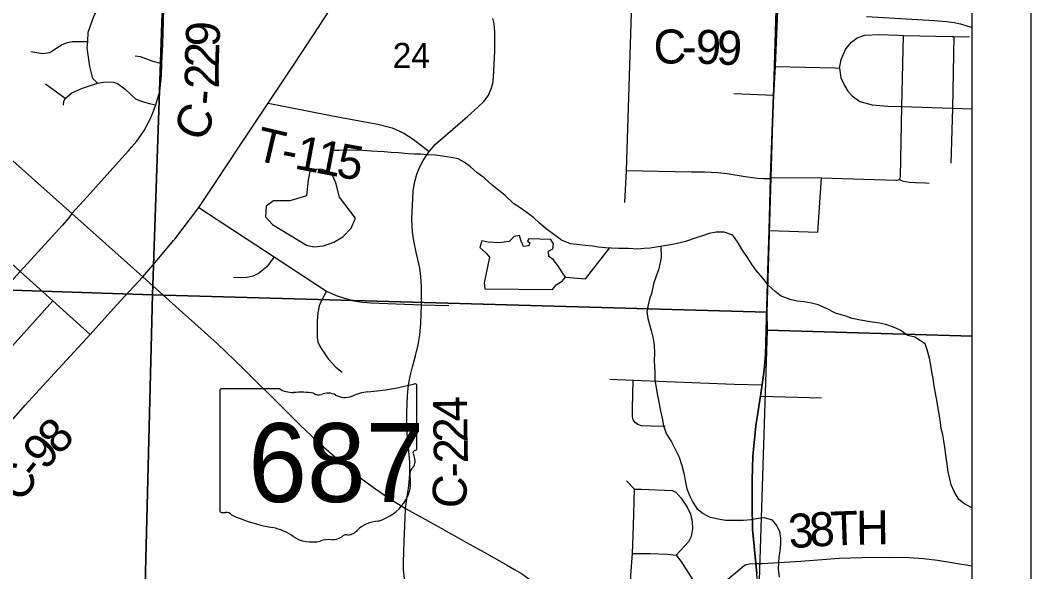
# Model space of a CAD drawing. Extents: x 0 to 34, y 0 to 22.
# Drawn here: x 8.046 to 9.735, y 16.375 to 17.297 of the extents above; entities that cross this region are included whole.
import ezdxf

# ---------------------------------------------------------------- set-up
doc = ezdxf.new("R2010")
doc.units = 0
for name, color, linetype in [('GM_X_Corporation', 7, 'Continuous'), ('GM_X_County_Road', 7, 'Continuous'), ('GM_X_County_Road_Text', 7, 'Continuous'), ('GM_X_Interchange_Ramps', 7, 'Continuous'), ('GM_X_Minor_Lake', 7, 'Continuous'), ('GM_X_Minor_River', 7, 'Continuous'), ('GM_X_Section_Text', 7, 'Continuous'), ('GM_X_State_Location', 7, 'Continuous'), ('GM_X_State_Route', 7, 'Continuous'), ('GM_X_State_Shield', 7, 'Continuous'), ('GM_X_Township_Road', 7, 'Continuous'), ('GM_X_Township_Road_Text', 7, 'Continuous'), ('SH_Data', 7, 'Continuous')]:
    doc.layers.add(name, color=color, linetype=linetype)

msp = doc.modelspace()

# ---------------------------------------------------------------- linework, layer by layer
at = {"layer": 'GM_X_Corporation'}
for points in [[(7.1023, 20.9204), (2.837, 20.9204), (2.837, 14.1204), (9.637, 14.1204), (9.637, 20.9204), (9.4036, 20.9204), (9.4022, 20.8667), (9.2273, 20.8723), (9.1354, 20.8749), (9.124, 20.8753), (8.9858, 20.878), (8.9676, 20.8785), (8.8663, 20.881), (8.6259, 20.8892), (8.5535, 20.8914), (8.5421, 20.8915), (8.4667, 20.8934), (8.0602, 20.9055), (7.9522, 20.9084), (7.1104, 20.9188)], [(8.3013, 17.8445), (8.2669, 16.8377), (7.2756, 16.8704), (7.31, 17.8806)], [(8.3013, 17.8445), (9.3232, 17.8175), (9.3224, 17.7834), (9.2937, 16.8089), (8.2669, 16.8377)], [(9.637, 16.7685), (9.637, 17.7759), (9.3224, 17.7834), (9.2937, 16.8089), (9.2941, 16.7789)], [(7.2756, 16.8704), (8.2669, 16.8377), (8.2409, 15.8234), (7.2356, 15.8559)], [(8.2669, 16.8377), (9.2937, 16.8089), (9.2941, 16.7789), (9.2625, 15.7858), (8.2409, 15.8234)], [(9.637, 15.7721), (9.637, 16.7685), (9.2941, 16.7789), (9.2625, 15.7858)]]:
    msp.add_lwpolyline(points, close=True, dxfattribs=at)
for points in [[(9.637, 14.7553), (9.637, 20.8621)], [(9.3114, 17.3124), (9.3077, 17.2197), (9.305, 17.1721), (9.2999, 17.0342), (9.2999, 17.0328), (9.2978, 16.9456), (9.2955, 16.8776), (9.2915, 16.7373), (9.2893, 16.7123), (9.2861, 16.6878), (9.2832, 16.6688), (9.2753, 16.6189), (9.27, 16.568), (9.2692, 16.5283), (9.2692, 16.4875), (9.2695, 16.4459), (9.2753, 16.389), (9.277, 16.3719)], [(9.277, 16.3719), (9.2753, 16.389), (9.2695, 16.4459), (9.2692, 16.4875), (9.2692, 16.5283), (9.27, 16.568), (9.2753, 16.6189), (9.2832, 16.6688), (9.2861, 16.6878), (9.2893, 16.7123), (9.2915, 16.7373), (9.2955, 16.8776), (9.2978, 16.9456), (9.2999, 17.0328), (9.2999, 17.0342), (9.305, 17.1721), (9.3077, 17.2197), (9.3114, 17.3124)]]:
    msp.add_lwpolyline(points, dxfattribs=at)
at = {"layer": 'GM_X_County_Road'}
for points in [[(8.2322, 17.085), (8.2404, 17.0945), (8.2529, 17.1125), (8.263, 17.1315), (8.2686, 17.1447), (8.2725, 17.1552), (8.2757, 17.1669), (8.2788, 17.1781), (8.2815, 17.2043), (8.282, 17.224), (8.2827, 17.2365), (8.2837, 17.2555), (8.289, 17.4375), (8.2914, 17.5073), (8.2971, 17.722)], [(9.3084, 17.2321), (9.3116, 17.3118), (9.3117, 17.3152), (9.3116, 17.322), (9.313, 17.3683), (9.3162, 17.4807)], [(8.3019, 16.9283), (8.3038, 16.9306), (8.3439, 16.9836), (8.3711, 17.024), (8.4108, 17.0845), (8.4598, 17.1583), (8.5, 17.2183), (8.5356, 17.2723), (8.5918, 17.3583), (8.6122, 17.3882), (8.6251, 17.4058)], [(8.6898, 16.4804), (8.6919, 16.496), (8.6951, 16.5183), (8.6969, 16.5376), (8.6968, 16.5582), (8.6952, 16.5766), (8.6926, 16.6062), (8.6919, 16.6408), (8.693, 16.6693), (8.6949, 16.6871), (8.6973, 16.702), (8.7011, 16.7176), (8.7063, 16.7358), (8.7109, 16.754), (8.7137, 16.7707), (8.7154, 16.7897), (8.7163, 16.8211), (8.7161, 16.8511), (8.715, 16.8686), (8.7135, 16.8825), (8.7073, 16.9093), (8.7037, 16.9279), (8.7011, 16.9433), (8.7003, 16.9641), (8.7022, 17.0112), (8.7045, 17.0251), (8.7086, 17.0392), (8.7137, 17.0518), (8.7193, 17.0623), (8.7292, 17.0773), (8.7399, 17.0895), (8.7769, 17.1218), (8.7931, 17.1359), (8.8107, 17.1513), (8.8212, 17.1614), (8.8282, 17.1717), (8.833, 17.1822), (8.8355, 17.1909), (8.8368, 17.2017), (8.8387, 17.2449), (8.8392, 17.2776), (8.8379, 17.2909), (8.8357, 17.2997)], [(9.27, 16.5575), (9.2702, 16.5675), (9.2755, 16.6183), (9.2834, 16.6682), (9.2863, 16.6872), (9.2895, 16.7117), (9.2917, 16.7368), (9.2957, 16.8771), (9.298, 16.945), (9.3001, 17.0323), (9.3001, 17.0336), (9.3052, 17.1715), (9.3079, 17.2192), (9.3084, 17.2321)], [(8.1319, 16.9735), (8.1576, 17.0017), (8.2099, 17.0598), (8.2265, 17.0785), (8.2322, 17.085)], [(8.2503, 16.8678), (8.2773, 16.899), (8.3019, 16.9283)], [(7.8215, 16.3345), (7.8745, 16.4095), (7.8951, 16.4388), (7.9345, 16.4973), (7.9798, 16.5613), (8.0233, 16.618), (8.0538, 16.6531), (8.0831, 16.6854), (8.1425, 16.7499), (8.1623, 16.7717), (8.2065, 16.8203), (8.2503, 16.8678)], [(9.2755, 16.3885), (9.2697, 16.4453), (9.2694, 16.487), (9.2694, 16.5278), (9.27, 16.5575)], [(8.6865, 16.391), (8.6875, 16.4261), (8.689, 16.4649), (8.6898, 16.4804)], [(8.7557, 15.8512), (8.7546, 15.867), (8.7537, 15.8789), (8.7508, 15.9143), (8.7479, 15.947), (8.7472, 15.9777), (8.7487, 16.0502), (8.7492, 16.0794), (8.748, 16.1083), (8.7461, 16.1243), (8.7434, 16.1411), (8.7383, 16.1623), (8.7241, 16.213), (8.7053, 16.2774), (8.6958, 16.3127), (8.6918, 16.331), (8.6898, 16.3442), (8.688, 16.3634), (8.6865, 16.3782), (8.6864, 16.39), (8.6865, 16.391)], [(9.2711, 16.0327), (9.2759, 16.1303), (9.2777, 16.1911), (9.2793, 16.2525), (9.2797, 16.3303), (9.2772, 16.3713), (9.2755, 16.3885)], [(9.2755, 16.3885), (9.2857, 16.3886), (9.3505, 16.3928), (9.4145, 16.3977), (9.4529, 16.3988), (9.4993, 16.3993), (9.5317, 16.3986), (9.5555, 16.397), (9.5788, 16.3944), (9.637, 16.3849)]]:
    msp.add_lwpolyline(points, dxfattribs=at)
at = {"layer": 'GM_X_Interchange_Ramps'}
msp.add_lwpolyline([(9.4601, 17.303), (9.5742, 17.296), (9.5938, 17.2947), (9.6071, 17.2927), (9.6174, 17.2907), (9.628, 17.2876), (9.637, 17.2843)], dxfattribs=at)
at = {"layer": 'GM_X_Minor_Lake'}
for points in [[(8.5794, 17.0012), (8.573, 17.025), (8.5656, 17.0424), (8.5488, 17.0479), (8.5302, 17.0469), (8.5267, 17.0297), (8.524, 17.0031), (8.4964, 16.9947), (8.4691, 16.9951), (8.4567, 16.9862), (8.4554, 16.9683), (8.467, 16.9552), (8.524, 16.9206), (8.5362, 16.9178), (8.5528, 16.9195), (8.5698, 16.9258), (8.5849, 16.9348), (8.5987, 16.9494), (8.6061, 16.9659)], [(8.6061, 16.9659), (8.5794, 17.0012)], [(8.9355, 16.8466), (8.9414, 16.8547), (8.9516, 16.8605), (8.9572, 16.8671), (8.9533, 16.8727), (8.9444, 16.887), (8.9367, 16.8968), (8.929, 16.902), (8.9289, 16.9107), (8.9361, 16.9146), (8.9371, 16.923), (8.9324, 16.9302), (8.8956, 16.9315), (8.8938, 16.9277), (8.8976, 16.9244), (8.8958, 16.9198), (8.8867, 16.9185), (8.8828, 16.9276), (8.88, 16.937), (8.8713, 16.9354), (8.8631, 16.9269), (8.8464, 16.9244), (8.8278, 16.9257), (8.8171, 16.9278), (8.8139, 16.9171), (8.8243, 16.9074), (8.83, 16.9006), (8.8211, 16.8579), (8.822, 16.8477)], [(8.822, 16.8477), (8.9355, 16.8466)]]:
    msp.add_lwpolyline(points, dxfattribs=at)
at = {"layer": 'GM_X_Minor_River'}
for points in [[(8.8813, 16.983), (8.8706, 16.9901), (8.8563, 17.0036), (8.8452, 17.0129), (8.8345, 17.0211), (8.821, 17.0331), (8.8095, 17.0417), (8.7984, 17.0514), (8.7877, 17.0596), (8.7774, 17.0648), (8.7659, 17.0673), (8.7515, 17.0693), (8.7397, 17.0711), (8.7253, 17.072), (8.7154, 17.0726), (8.7044, 17.0729), (8.6938, 17.0735), (8.6778, 17.0748), (8.6657, 17.0757), (8.6539, 17.0767), (8.6421, 17.0773), (8.6326, 17.0779), (8.6174, 17.0789), (8.5939, 17.0793), (8.5787, 17.0791), (8.5643, 17.0792)], [(9.637, 16.4809), (9.6366, 16.4815), (9.6243, 16.4885), (9.6147, 16.4956), (9.6066, 16.5092), (9.6019, 16.5201), (9.5995, 16.5303), (9.5967, 16.5417), (9.5945, 16.5588), (9.5932, 16.5705), (9.5912, 16.5826), (9.5895, 16.5936), (9.5879, 16.6035), (9.5851, 16.6141), (9.5838, 16.6243), (9.5821, 16.6353), (9.5801, 16.6475), (9.5784, 16.6585), (9.5755, 16.6736), (9.5735, 16.6854), (9.5718, 16.6979), (9.5694, 16.7089), (9.5677, 16.7199), (9.5656, 16.7316), (9.5617, 16.7456), (9.5581, 16.7558), (9.5413, 16.767), (9.5295, 16.7699), (9.5168, 16.7784), (9.5054, 16.7836), (9.4928, 16.7883), (9.4821, 16.7901), (9.4662, 16.7925), (9.4502, 16.7953), (9.4361, 16.7982), (9.4258, 16.8018), (9.4087, 16.8073), (9.3934, 16.8147), (9.3797, 16.8209), (9.3686, 16.8238), (9.3561, 16.8259), (9.3443, 16.8273), (9.3325, 16.8298), (9.3176, 16.8353), (9.3077, 16.8435), (9.2965, 16.8532), (9.2869, 16.8656), (9.2765, 16.8776), (9.2691, 16.8878), (9.2614, 16.9002), (9.2517, 16.9138), (9.2455, 16.9247), (9.237, 16.9375), (9.2225, 16.9426), (9.2088, 16.9424), (9.1975, 16.94), (9.1862, 16.9364), (9.1756, 16.9332), (9.1578, 16.9269), (9.1465, 16.9241), (9.1359, 16.922), (9.1261, 16.92), (9.112, 16.9179), (9.0984, 16.9158), (9.0886, 16.9149), (9.0776, 16.9143), (9.0624, 16.9149), (9.0461, 16.9154), (9.0332, 16.9156), (9.0237, 16.9162), (9.0123, 16.9172), (9.0028, 16.919), (8.9902, 16.9203), (8.9804, 16.9213), (8.9652, 16.923), (8.9503, 16.9293), (8.9353, 16.9401), (8.9246, 16.9479), (8.9135, 16.9576), (8.9039, 16.9666), (8.8908, 16.9763), (8.8813, 16.983)], [(8.9572, 16.8671), (8.9906, 16.8645), (9.0306, 16.9158)], [(9.1167, 16.9186), (9.1172, 16.9001), (9.1129, 16.881), (9.1085, 16.8692), (9.1042, 16.8562), (9.1006, 16.8402), (9.0977, 16.8307), (9.0952, 16.8211), (9.093, 16.8101), (9.0947, 16.7983), (9.1003, 16.7779), (9.1031, 16.7669), (9.1052, 16.754), (9.1057, 16.7396), (9.1055, 16.7286), (9.1057, 16.7175), (9.1062, 16.7077), (9.1067, 16.6959), (9.108, 16.6864), (9.1104, 16.6724), (9.1125, 16.6618), (9.1154, 16.6459), (9.1186, 16.6315), (9.1207, 16.619), (9.1262, 16.6046), (9.1343, 16.5922), (9.1394, 16.582), (9.1472, 16.5665), (9.1515, 16.5525), (9.1555, 16.5374), (9.1572, 16.5275), (9.16, 16.5135), (9.1647, 16.5014), (9.1702, 16.4912), (9.1768, 16.4807), (9.1875, 16.4721), (9.1971, 16.4669), (9.2096, 16.4641), (9.2248, 16.4612), (9.2393, 16.4611), (9.2544, 16.4613), (9.2673, 16.4622), (9.2794, 16.4647), (9.29, 16.4656), (9.3022, 16.4616), (9.3103, 16.4518), (9.3146, 16.442), (9.3163, 16.431), (9.3164, 16.4204), (9.3154, 16.4101), (9.3137, 16.3998), (9.3128, 16.3796), (9.3145, 16.3656)]]:
    msp.add_lwpolyline(points, dxfattribs=at)
at = {"layer": 'GM_X_State_Route'}
msp.add_line((8.3168, 16.8083), (8.3316, 16.795), dxfattribs=at)
for points in [[(7.7935, 17.2806), (7.8004, 17.2734), (7.8414, 17.233), (7.8814, 17.1971), (7.9807, 17.1082), (8.1319, 16.9735), (8.2503, 16.8678), (8.3168, 16.8083)], [(8.3316, 16.795), (8.3752, 16.7559), (8.4181, 16.7144), (8.4897, 16.6437), (8.5132, 16.6205), (8.5428, 16.5921), (8.5796, 16.5597), (8.6171, 16.5298), (8.6396, 16.5133), (8.6521, 16.5047), (8.6644, 16.4961), (8.6898, 16.4804), (8.7441, 16.4504), (8.7916, 16.4239), (8.8213, 16.4074), (8.8583, 16.3867), (8.8719, 16.3787), (8.8834, 16.3717), (8.896, 16.363), (8.9057, 16.3552), (8.9153, 16.3465), (8.9343, 16.3289), (8.9639, 16.3015)]]:
    msp.add_lwpolyline(points, dxfattribs=at)
at = {"layer": 'GM_X_State_Shield'}
for p, q in [((8.379, 16.6774), (8.379, 16.4773)), ((8.4788, 16.6808), (8.3822, 16.6808)), ((8.7086, 16.5811), (8.7086, 16.6858)), ((8.7085, 16.5811), (8.7086, 16.5811))]:
    msp.add_line(p, q, dxfattribs=at)
for centre, major_axis, start_param, end_param in [((8.3828, 16.6778), (0.00382, 0), 1.712693, 3.28349), ((8.5017, 16.7041), (0.037, 0), 4.042523, 4.731795), ((8.514, 16.5685), (0.133, 0), 1.404758, 1.657858), ((8.6358, 16.6197), (0.0703, 0), 1.699011, 2.107814), ((8.5912, 16.9537), (0.3495, 0), 4.814394, 5.042369), ((8.7049, 16.6862), (0.00367, 0), 6.141152, 7.989035), ((8.5442, 16.6789), (0.0107, 0), 3.836095, 5.185415), ((8.5599, 16.6557), (0.0222, 0), 0.950623, 2.079405), ((8.5886, 16.6875), (0.0267, 0), 4.081561, 5.145723), ((8.7077, 16.5734), (0.00568, 0), 1.883978, 3.671073), ((8.7047, 16.5807), (0.00393, 0), 5.05454, 6.418171), ((8.6716, 16.5602), (0.0341, 0), 5.934695, 6.695948), ((8.7217, 16.5373), (0.0248, 0), 2.387724, 3.262537), ((8.6108, 16.524), (0.0874, 0), 5.101752, 6.440018), ((8.3828, 16.4768), (0.00385, 0), 3.00124, 4.508301), ((8.3834, 16.4973), (0.0294, 0), 4.665946, 4.897461), ((8.3894, 16.4657), (0.0106, 0), 0.519207, 1.627899), ((8.5232, 16.6455), (0.2524, 0), 4.195997, 4.488961), ((8.6476, 16.4211), (0.0479, 0), 1.647645, 2.488434), ((8.448, 16.3874), (0.079, 0), 0.823519, 1.323587), ((8.587, 16.4579), (0.0282, 0), 4.937069, 5.64225), ((8.5334, 16.4647), (0.0501, 0), 4.026481, 4.996735), ((8.5623, 16.3956), (0.0412, 0), 1.495662, 1.94098), ((8.566, 16.4498), (0.0267, 0), 4.691044, 5.507374), ((8.5902, 16.4304), (0.00752, 0), 1.147584, 2.315152)]:
    msp.add_ellipse(centre, major_axis=major_axis, ratio=0.8, start_param=start_param, end_param=end_param, dxfattribs=at)
at = {"layer": 'GM_X_Township_Road'}
for p, q in [((9.3079, 17.2192), (9.4074, 17.2169)), ((8.1204, 17.166), (8.0875, 17.19)), ((9.2385, 17.174), (9.3052, 17.1715)), ((9.3792, 16.9426), (9.3851, 17.0332)), ((9.298, 16.945), (9.3792, 16.9426)), ((9.2834, 16.6682), (9.3853, 16.6656))]:
    msp.add_line(p, q, dxfattribs=at)
for points in [[(8.1747, 17.1914), (8.1671, 17.1994), (8.1618, 17.2193), (8.1576, 17.2506), (8.1583, 17.2611), (8.1593, 17.2767), (8.1691, 17.3049), (8.1751, 17.3149), (8.1819, 17.3264), (8.1909, 17.3447), (8.1973, 17.3642), (8.2022, 17.3838), (8.2024, 17.3862), (8.2051, 17.4122), (8.2056, 17.4232), (8.2076, 17.4687), (8.2167, 17.5076)], [(9.0562, 16.9918), (9.0592, 17.0456), (9.0678, 17.3266)], [(9.4074, 17.2169), (9.4154, 17.2167), (9.4177, 17.231), (9.4255, 17.2487), (9.4354, 17.26), (9.4449, 17.2675), (9.4577, 17.2717), (9.4815, 17.2731), (9.5135, 17.2717)], [(9.5135, 17.2717), (9.5222, 17.2713), (9.6034, 17.2698)], [(9.5156, 17.0307), (9.517, 17.0348), (9.5194, 17.1523), (9.5222, 17.2713)], [(9.6064, 17.2697), (9.6039, 17.1497), (9.6014, 17.0578)], [(9.6034, 17.2698), (9.6064, 17.2697), (9.6327, 17.2692)], [(8.0632, 17.2445), (8.0733, 17.2426), (8.0827, 17.2411), (8.0949, 17.2429), (8.105, 17.2494), (8.1158, 17.2559), (8.1243, 17.2594), (8.1323, 17.261), (8.1583, 17.2611)], [(8.282, 17.224), (8.266, 17.2285), (8.2465, 17.2356), (8.2377, 17.2365)], [(9.4154, 17.2167), (9.4176, 17.2006), (9.4236, 17.1874), (9.429, 17.1784), (9.4361, 17.1702), (9.4494, 17.161), (9.4699, 17.1551), (9.4959, 17.1531), (9.5194, 17.1523), (9.6039, 17.1497), (9.637, 17.1487)], [(8.1176, 17.1546), (8.1184, 17.1609), (8.1204, 17.166), (8.1318, 17.1752), (8.1495, 17.183), (8.1747, 17.1914), (8.1848, 17.1931), (8.1948, 17.194), (8.2012, 17.1933), (8.2082, 17.1907), (8.2207, 17.1815), (8.2297, 17.1731), (8.2385, 17.1655), (8.2447, 17.1624), (8.2534, 17.1597), (8.261, 17.1577), (8.2725, 17.1552)], [(8.4598, 17.1583), (8.4827, 17.1534), (8.5677, 17.1369), (8.6126, 17.1287), (8.6431, 17.1229), (8.6673, 17.1169), (8.6868, 17.1077), (8.7022, 17.0978), (8.7292, 17.0773)], [(9.0592, 17.0456), (9.1676, 17.0435), (9.1893, 17.0432), (9.2118, 17.0424), (9.2274, 17.0406), (9.2541, 17.0359), (9.2654, 17.0343), (9.2778, 17.0329), (9.2882, 17.0323), (9.3001, 17.0323)], [(9.3001, 17.0336), (9.3851, 17.0332), (9.5095, 17.0293)], [(9.5095, 17.0293), (9.5114, 17.0293), (9.5156, 17.0307), (9.52, 17.0284), (9.525, 17.027), (9.5324, 17.0261), (9.5422, 17.0253), (9.5586, 17.025), (9.5651, 17.0244)], [(8.3439, 16.9836), (8.4699, 16.9011), (8.5576, 16.8438), (8.5737, 16.8366), (8.5891, 16.8315), (8.603, 16.8277), (8.6177, 16.8253), (8.6314, 16.8244), (8.7163, 16.8211), (8.7623, 16.8198)], [(8.1319, 16.9735), (8.1268, 16.9664), (8.1163, 16.954), (8.0456, 16.8769), (7.9421, 16.763)], [(8.1623, 16.7717), (8.1002, 16.8276), (8.0456, 16.8769), (8.0153, 16.9048), (8.0054, 16.9115), (7.996, 16.9153), (7.9838, 16.9178), (7.9487, 16.9183), (7.9406, 16.9167)], [(8.4699, 16.9011), (8.4576, 16.8845), (8.4437, 16.8734), (8.4349, 16.8692), (8.4244, 16.8666), (8.4139, 16.8659), (8.4019, 16.8666)], [(8.5576, 16.8438), (8.5488, 16.827), (8.5453, 16.8191), (8.5429, 16.8077), (8.5418, 16.7935), (8.5422, 16.7663), (8.5433, 16.7592), (8.5469, 16.7506), (8.5603, 16.7305), (8.5733, 16.7171), (8.5836, 16.7084)], [(7.9506, 16.6601), (7.9933, 16.7091), (8.1002, 16.8276)], [(9.031, 16.6968), (9.0703, 16.695), (9.2393, 16.6884), (9.2863, 16.6872)], [(9.1239, 16.6178), (9.1003, 16.6183), (9.0844, 16.6188), (9.078, 16.6208), (9.0741, 16.624), (9.0704, 16.6286), (9.0693, 16.6341), (9.069, 16.6475), (9.0703, 16.695)], [(9.0225, 16.2432), (9.0516, 16.2717), (9.0707, 16.2909), (9.0782, 16.2954), (9.0712, 16.3185), (9.067, 16.3373), (9.0662, 16.3502), (9.0665, 16.3684), (9.0689, 16.4056), (9.0705, 16.4514), (9.0724, 16.5127), (9.0588, 16.5267)], [(9.0724, 16.5127), (9.0837, 16.5131), (9.1355, 16.5105), (9.1417, 16.5079), (9.1506, 16.4977), (9.1605, 16.4826), (9.1663, 16.4712), (9.1689, 16.4584), (9.1693, 16.447), (9.1674, 16.4338), (9.1627, 16.425), (9.1421, 16.4026)], [(9.0689, 16.4056), (9.099, 16.4055), (9.1274, 16.4044), (9.1421, 16.4026), (9.1498, 16.3923), (9.163, 16.3724), (9.1811, 16.3438)], [(9.0782, 16.2954), (9.0855, 16.283), (9.0899, 16.2753), (9.092, 16.2652), (9.0961, 16.2747), (9.0993, 16.2794), (9.1036, 16.2845), (9.117, 16.2993), (9.124, 16.306), (9.1312, 16.312), (9.1508, 16.3261), (9.1695, 16.338), (9.1811, 16.3438), (9.1951, 16.3484), (9.2128, 16.3539), (9.2207, 16.3568), (9.2286, 16.3622), (9.2448, 16.376), (9.253, 16.3833), (9.2577, 16.3864), (9.2644, 16.3883), (9.2755, 16.3885)]]:
    msp.add_lwpolyline(points, dxfattribs=at)
at = {"layer": 'SH_Data'}
msp.add_line((9.7349, 21.0001), (9.7349, 14.0001), dxfattribs=at)

# ---------------------------------------------------------------- texts
at = {"layer": 'GM_X_County_Road_Text'}
for s, rotation, p in [('9', 87.5014, (8.3784, 17.2516)), ('C', 1.0694, (9.1048, 17.2238)), ('9', 358.0534, (9.174, 17.2244)), ('9', 357.147, (9.2087, 17.2232)), ('2', 88.173, (8.3773, 17.2168)), ('-', 359.2662, (9.151, 17.2247)), ('2', 90.618, (8.3777, 17.1825)), ('-', 85.2208, (8.3756, 17.1534)), ('C', 65.9527, (8.3514, 17.0907)), ('4', 91.0058, (8.7929, 16.6266)), ('8', 46.0444, (8.1101, 16.568)), ('2', 90.9704, (8.7934, 16.5915)), ('9', 47.3031, (8.0867, 16.5427)), ('2', 90.8223, (8.794, 16.5564)), ('C', 55.328, (8.0474, 16.4881)), ('-', 51.7063, (8.0732, 16.5254)), ('-', 90.9613, (8.7943, 16.5331)), ('C', 82.9021, (8.7881, 16.4781)), ('3', 4.0678, (9.3316, 16.4139)), ('8', 3.4627, (9.3664, 16.4164)), ('T', 2.0104, (9.4009, 16.4185)), ('H', 0.7395, (9.4431, 16.42))]:
    msp.add_text(s, height=0.0568, rotation=rotation, dxfattribs=at).set_placement(p)
at = {"layer": 'GM_X_Section_Text'}
msp.add_text('24', height=0.04186, rotation=0, dxfattribs=at).set_placement((8.6682, 17.217))
at = {"layer": 'GM_X_State_Location'}
for s in ['s', 'r']:
    msp.add_text(s, height=0.000189, dxfattribs=at).set_placement((8.5401, 16.564))
msp.add_text('687', height=0.000189, rotation=0, dxfattribs=at).set_placement((8.4732, 16.5503))
at = {"layer": 'GM_X_State_Shield'}
msp.add_text('687', height=0.13184, dxfattribs=at).set_placement((8.4268, 16.4914))
at = {"layer": 'GM_X_Township_Road_Text'}
for s, rotation, p in [('T', 346.8037, (8.4356, 17.0638)), ('1', 349.1007, (8.5023, 17.0491)), ('1', 349.1661, (8.5367, 17.0425)), ('5', 349.916, (8.5719, 17.0357)), ('-', 348.9019, (8.4792, 17.0536))]:
    msp.add_text(s, height=0.0568, rotation=rotation, dxfattribs=at).set_placement(p)

doc.saveas('drawing.dxf')
